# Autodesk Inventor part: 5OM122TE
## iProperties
Created: 2007-05
Part Number: 5OM122TE
Document SubType Name: Modeling
Designer: Darius
Author: Darius
Translation Standard: STEP AP203
File Name: 5OM122TE.STEP
Preprocessor: SolidWorks 2003240
Postprocessor: Build: 270, Release: 10 SP2 - Date: Mon 09/26/2005
Sent Units: MILLIMETERS
Uncertainty: 1e-05
